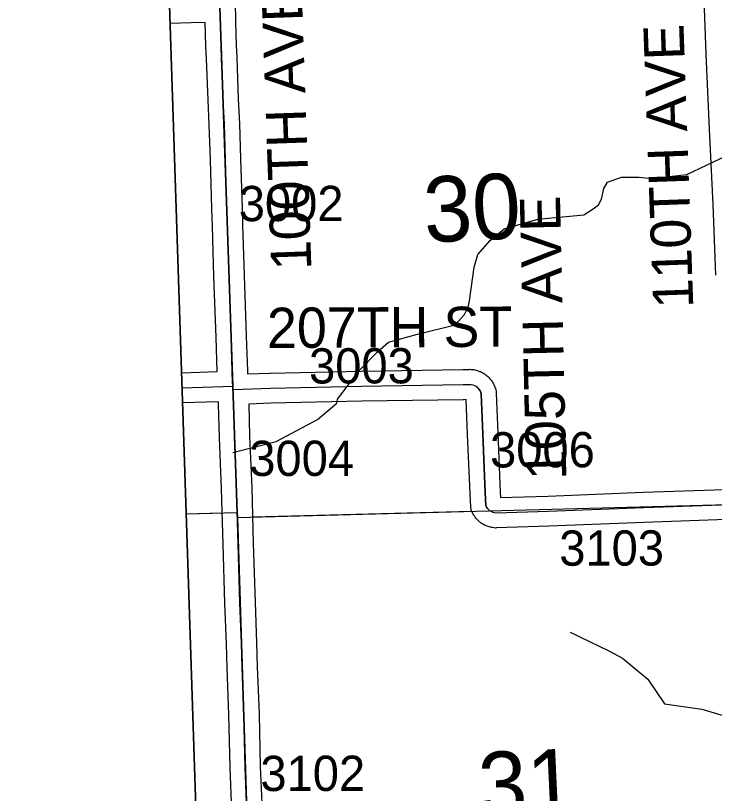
# Model space of a CAD drawing. Extents: x 128.7 to 185.5, y -21.4 to 12.6.
# Drawn here: x 133.689 to 135.078, y -7.251 to -5.706 of the extents above; entities that cross this region are included whole.
import ezdxf

# ---------------------------------------------------------------- set-up
doc = ezdxf.new("R2010")
doc.units = 0
for name, color, linetype in [('tdCoClipBndry', 7, 'Continuous'), ('tdCoCoBndry', 7, 'Continuous'), ('tdCoHydroRiver', 7, 'Continuous'), ('tdCoSecRdNmbr', 7, 'Continuous'), ('tdCoSecRdTxt', 7, 'Continuous'), ('tdCoSecRteBand', 7, 'Continuous'), ('tdCoSecRteCL', 7, 'Continuous'), ('tdCoSectLine', 7, 'Continuous'), ('tdCoSectLinePart', 7, 'Continuous'), ('tdCoSectNmbr', 7, 'Continuous'), ('tdCoSurfGravel', 7, 'Continuous'), ('tdCoTwpBndryShd', 7, 'Continuous')]:
    doc.layers.add(name, color=color, linetype=linetype)

msp = doc.modelspace()

# ---------------------------------------------------------------- linework, layer by layer
at = {"layer": 'tdCoClipBndry'}
msp.add_lwpolyline([(134.0612, -7.7025), (133.8962, -2.6807), (133.6887, 4.3446), (133.6938, 4.3792), (133.7053, 4.4028), (133.7226, 4.4226), (133.7445, 4.4372), (133.7868, 4.4475), (134.771, 4.4649), (135.7559, 4.4935), (136.7866, 4.5129), (139.7725, 4.5879), (146.7594, 4.806), (147.7608, 4.8492), (149.7557, 4.9088), (150.75, 4.946), (153.7332, 5.0633)], dxfattribs=at)
at = {"layer": 'tdCoCoBndry'}
for p, q in [((134.095, -5.6895), (134.1294, -6.6932)), ((134.1294, -6.6932), (134.095, -5.6895)), ((134.1294, -6.6932), (134.1297, -6.7029)), ((134.1297, -6.7029), (134.1294, -6.6932)), ((134.1297, -6.7029), (134.1615, -7.6994)), ((134.1615, -7.6994), (134.1297, -6.7029))]:
    msp.add_line(p, q, dxfattribs=at)
for points in [[(134.1615, -7.6994), (134.1297, -6.7029), (134.1294, -6.6932), (134.095, -5.6895), (134.0611, -4.6883), (134.0307, -3.6816), (133.9965, -2.6778), (133.9676, -1.6731), (133.9395, -0.6703), (133.9071, 0.3357), (133.8784, 1.3376), (133.8476, 2.341), (133.8192, 3.3421), (133.789, 4.3475), (134.7737, 4.365), (135.7592, 4.3936), (135.7859, 4.3937), (136.7735, 4.4131), (136.7891, 4.4129), (137.7728, 4.4375)], [(133.7886, 4.3475), (133.8188, 3.3421), (133.8473, 2.341), (133.878, 1.3376), (133.9067, 0.3357), (133.9391, -0.6703), (133.9673, -1.6731), (133.9961, -2.6778), (134.0303, -3.6816), (134.0608, -4.6883), (134.0947, -5.6895), (134.129, -6.6932), (134.1293, -6.7029), (134.1612, -7.6994), (134.1875, -8.683), (134.2186, -9.7062), (134.2417, -10.7094), (134.275, -11.7191), (134.2997, -12.7212), (134.329, -13.723)], [(134.1615, -7.6994), (134.1297, -6.7029), (134.1294, -6.6932), (134.095, -5.6895), (134.0611, -4.6883), (134.0307, -3.6816), (133.9965, -2.6778), (133.9676, -1.6731), (133.8665, -1.6741), (133.8962, -2.6807), (134.0612, -7.7025)]]:
    msp.add_lwpolyline(points, dxfattribs=at)
at = {"layer": 'tdCoHydroRiver'}
for points in [[(134.1206, -6.5738), (134.2067, -6.5523), (134.2891, -6.5088), (134.3275, -6.4761), (134.3289, -6.4682), (134.3729, -6.4101), (134.4082, -6.3743), (134.4297, -6.3547), (134.4876, -6.3388), (134.5628, -6.3208), (134.5811, -6.2997), (134.5886, -6.2853), (134.5913, -6.2726), (134.6004, -6.206), (134.6075, -6.1806), (134.632, -6.153), (134.6597, -6.1301), (134.727, -6.1107), (134.8182, -6.1017), (134.8368, -6.0901), (134.8476, -6.0819), (134.8536, -6.0707), (134.8577, -6.05), (134.8652, -6.0372), (134.8933, -6.0269), (134.928, -6.0274), (134.9535, -6.0299), (135.0229, -6.0218), (135.101, -5.9851)], [(134.791, -6.9308), (134.8679, -6.968), (134.8952, -6.9829), (134.9453, -7.0241), (134.9783, -7.0736), (135.0528, -7.084), (135.126, -7.1055)]]:
    msp.add_lwpolyline(points, dxfattribs=at)
at = {"layer": 'tdCoSecRteBand'}
for points in [[(135.0807, -6.2218), (135.0753, -6.0816), (135.0682, -5.932), (135.0682, -5.932), (135.0682, -5.9319), (135.0615, -5.7827), (135.0615, -5.7826), (135.0615, -5.7825), (135.0568, -5.6548)], [(134.125, -5.6888), (134.1256, -5.7076), (134.1256, -5.7076), (134.1256, -5.7076), (134.1259, -5.7187), (134.1259, -5.7187), (134.127, -5.765), (134.1283, -5.7895), (134.1283, -5.7897), (134.1283, -5.7898), (134.1315, -5.8714), (134.1337, -5.9209), (134.1337, -5.9211), (134.1337, -5.9212), (134.1359, -5.9908), (134.1359, -5.9908), (134.1359, -5.9908), (134.1389, -6.0879), (134.1401, -6.1221), (134.1401, -6.1222), (134.1401, -6.1223), (134.1431, -6.2228), (134.1473, -6.3431), (134.1473, -6.3431), (134.1473, -6.3432), (134.1495, -6.4116), (134.1497, -6.4116), (134.1499, -6.4179), (134.1943, -6.4162), (134.1946, -6.4162), (134.1948, -6.4162), (134.3756, -6.4122), (134.3757, -6.4122), (134.3758, -6.4122), (134.5776, -6.4093), (134.5873, -6.409), (134.5902, -6.4089), (134.5922, -6.4088), (134.5942, -6.409), (134.5974, -6.4093), (134.5993, -6.4095), (134.6013, -6.4099), (134.6044, -6.4106), (134.6063, -6.4111), (134.6082, -6.4118), (134.6111, -6.4129), (134.613, -6.4135), (134.6147, -6.4145), (134.6175, -6.416), (134.6193, -6.4169), (134.6209, -6.418), (134.6215, -6.4185), (134.6215, -6.4185), (134.6215, -6.4185), (134.6235, -6.4199), (134.6251, -6.421), (134.6266, -6.4224), (134.6289, -6.4246), (134.6303, -6.4259), (134.6316, -6.4275), (134.6336, -6.4299), (134.6348, -6.4314), (134.6359, -6.4331), (134.6375, -6.4358), (134.6386, -6.4375), (134.6394, -6.4393), (134.6407, -6.4422), (134.6415, -6.444), (134.6421, -6.4459), (134.643, -6.449), (134.6441, -6.4526), (134.6442, -6.4564), (134.6472, -6.536), (134.6521, -6.6528), (134.6527, -6.6637)], [(134.019, -6.4157), (134.0895, -6.4135), (134.0873, -6.3452), (134.0831, -6.2249), (134.0831, -6.2248), (134.0831, -6.2247), (134.0801, -6.1242), (134.0789, -6.09), (134.0789, -6.0899), (134.0789, -6.0898), (134.076, -5.9927), (134.0737, -5.9234), (134.0715, -5.874), (134.0715, -5.8739), (134.0715, -5.8738), (134.0683, -5.7923), (134.0671, -5.7676), (134.0671, -5.7672), (134.0671, -5.7669), (134.0659, -5.72), (134.0379, -5.7206), (133.9962, -5.7218)], [(134.1186, -7.2875), (134.1152, -7.2001), (134.1152, -7.1998), (134.1152, -7.1996), (134.1127, -7.0952), (134.1092, -7.0017), (134.1092, -7.0016), (134.1092, -7.0016), (134.1078, -6.9543), (134.1048, -6.8737), (134.1048, -6.8737), (134.1048, -6.8736), (134.1011, -6.7569), (134.1011, -6.7569), (134.1011, -6.7568), (134.0981, -6.6463), (134.094, -6.5449), (134.094, -6.5447), (134.0939, -6.5444), (134.0922, -6.478), (134.092, -6.4734), (134.0209, -6.4757)], [(135.1015, -6.7074), (134.9384, -6.7131), (134.7488, -6.7205), (134.7487, -6.7205), (134.7486, -6.7205), (134.6448, -6.724), (134.6425, -6.7241), (134.6403, -6.7238), (134.637, -6.7234), (134.635, -6.7232), (134.6329, -6.7226), (134.6298, -6.7218), (134.6278, -6.7213), (134.6258, -6.7205), (134.6228, -6.7192), (134.6209, -6.7184), (134.6191, -6.7173), (134.6163, -6.7156), (134.6145, -6.7146), (134.6129, -6.7133), (134.6115, -6.7122), (134.6104, -6.7112), (134.6087, -6.7099), (134.6073, -6.7084), (134.6051, -6.706), (134.6036, -6.7045), (134.6024, -6.7028), (134.6006, -6.7001), (134.5993, -6.6984), (134.5984, -6.6966), (134.5969, -6.6937), (134.594, -6.688), (134.5936, -6.6817), (134.5922, -6.656), (134.5921, -6.6558), (134.5921, -6.6556), (134.5872, -6.5384), (134.5872, -6.5384), (134.5872, -6.5383), (134.5846, -6.4691), (134.5789, -6.4693), (134.5788, -6.4693), (134.5787, -6.4693), (134.3768, -6.4722), (134.1964, -6.4762), (134.1522, -6.4779), (134.1539, -6.5426), (134.1581, -6.644), (134.1581, -6.6442), (134.1581, -6.6445), (134.1611, -6.7551), (134.1648, -6.8716), (134.1677, -6.9522), (134.1677, -6.9523), (134.1677, -6.9523), (134.1692, -6.9996), (134.1727, -7.0932), (134.1727, -7.0934), (134.1727, -7.0936), (134.1751, -7.1979), (134.1786, -7.2855)], [(134.6527, -6.6637), (134.7466, -6.6606), (134.9361, -6.6532), (134.9362, -6.6532), (134.9362, -6.6532), (135.0986, -6.6475)]]:
    msp.add_lwpolyline(points, dxfattribs=at)
at = {"layer": 'tdCoSecRteCL'}
for p in [(134.0199, -6.4457), (134.1211, -6.449)]:
    msp.add_line(p, (134.1207, -6.4425), dxfattribs=at)
for points in [[(134.1207, -6.4425), (134.1202, -6.4351), (134.1173, -6.3442), (134.1131, -6.2238), (134.1101, -6.1232), (134.1089, -6.0889), (134.1059, -5.9917), (134.1037, -5.9222), (134.1015, -5.8726), (134.0983, -5.791), (134.0971, -5.7661), (134.0956, -5.7084), (134.095, -5.6895)], [(134.1211, -6.449), (134.1955, -6.4462), (134.3762, -6.4422), (134.5782, -6.4393), (134.5883, -6.439), (134.5915, -6.4389), (134.5946, -6.4392), (134.5977, -6.4399), (134.6007, -6.441), (134.6035, -6.4425), (134.6041, -6.4429), (134.6061, -6.4443), (134.6084, -6.4465), (134.6104, -6.4489), (134.612, -6.4516), (134.6133, -6.4545), (134.6142, -6.4575), (134.6172, -6.5372), (134.6221, -6.6543), (134.6236, -6.68), (134.6251, -6.6828), (134.6269, -6.6855), (134.6292, -6.6879), (134.6303, -6.6888), (134.6317, -6.6899), (134.6345, -6.6915), (134.6375, -6.6928), (134.6406, -6.6936), (134.6438, -6.694), (134.7476, -6.6906), (134.9373, -6.6832), (135.1299, -6.6764)], [(134.1486, -7.2867), (134.1451, -7.1989), (134.1427, -7.0943), (134.1392, -7.0006), (134.1377, -6.9533), (134.1348, -6.8726), (134.1311, -6.756), (134.1281, -6.6453), (134.1239, -6.5437), (134.1217, -6.4586), (134.1211, -6.449)]]:
    msp.add_lwpolyline(points, dxfattribs=at)
at = {"layer": 'tdCoSectLine'}
for points in [[(134.0947, -5.6895), (134.129, -6.6932)], [(134.1293, -6.7029), (135.1295, -6.6764)], [(134.0282, -6.6961), (134.129, -6.6932)], [(134.129, -6.6932), (134.1293, -6.7029)], [(134.1293, -6.7029), (134.1612, -7.6994)]]:
    msp.add_lwpolyline(points, dxfattribs=at)
at = {"layer": 'tdCoSectLinePart'}
for points in [[(134.1596, -6.7021), (134.5957, -6.6906)], [(134.0282, -6.6961), (134.099, -6.6941)]]:
    msp.add_lwpolyline(points, dxfattribs=at)
at = {"layer": 'tdCoSurfGravel'}
msp.add_line((134.0199, -6.4457), (134.1207, -6.4425), dxfattribs=at)
for points in [[(134.1486, -7.2867), (134.1451, -7.1989), (134.1427, -7.0943), (134.1392, -7.0006), (134.1377, -6.9533), (134.1348, -6.8726), (134.1311, -6.756), (134.1281, -6.6453), (134.1239, -6.5437), (134.1217, -6.4586), (134.1211, -6.449), (134.1207, -6.4425), (134.1202, -6.4351), (134.1173, -6.3442), (134.1131, -6.2238), (134.1101, -6.1232), (134.1089, -6.0889), (134.1059, -5.9917), (134.1037, -5.9222), (134.1015, -5.8726), (134.0983, -5.791), (134.0971, -5.7661), (134.0956, -5.7084), (134.095, -5.6895)], [(134.1211, -6.449), (134.1955, -6.4462), (134.3762, -6.4422), (134.5782, -6.4393), (134.5883, -6.439), (134.5915, -6.4389), (134.5946, -6.4392), (134.5977, -6.4399), (134.6007, -6.441), (134.6035, -6.4425), (134.6041, -6.4429)], [(134.6303, -6.6888), (134.6292, -6.6879), (134.6269, -6.6855), (134.6251, -6.6828), (134.6236, -6.68), (134.6221, -6.6543), (134.6172, -6.5372), (134.6142, -6.4575), (134.6133, -6.4545), (134.612, -6.4516), (134.6104, -6.4489), (134.6084, -6.4465), (134.6061, -6.4443), (134.6041, -6.4429)], [(134.6303, -6.6888), (134.6317, -6.6899), (134.6345, -6.6915), (134.6375, -6.6928), (134.6406, -6.6936), (134.6438, -6.694), (134.7476, -6.6906), (134.9373, -6.6832), (135.1299, -6.6764)]]:
    msp.add_lwpolyline(points, dxfattribs=at)
at = {"layer": 'tdCoTwpBndryShd'}
msp.add_lwpolyline([(133.7886, 4.3475), (133.8188, 3.3421), (133.8473, 2.341), (133.878, 1.3376), (133.9067, 0.3357), (133.9391, -0.6703), (133.9673, -1.6731), (133.9961, -2.6778), (134.0303, -3.6816), (134.0608, -4.6883), (134.0947, -5.6895), (134.129, -6.6932), (134.1293, -6.7029), (134.1612, -7.6994)], dxfattribs=at)

# ---------------------------------------------------------------- texts
at = {"layer": 'tdCoSecRdNmbr'}
for s, rotation, p in [('3002', 0.1021, (134.1324, -6.1146)), ('3003', 0.1023, (134.2721, -6.4371)), ('3006', 0.1023, (134.6319, -6.6038)), ('3004', 0.1021, (134.1533, -6.6208)), ('3103', 0.1026, (134.7694, -6.799)), ('3102', 0.1021, (134.1754, -7.2466))]:
    msp.add_text(s, height=0.07, rotation=rotation, dxfattribs=at).set_placement(p)
at = {"layer": 'tdCoSecRdTxt'}
for s, rotation, p in [('100TH AVE', 92, (134.2769, -6.2107)), ('110TH AVE', 92, (135.036, -6.2867)), ('105TH AVE', 91.3087, (134.7837, -6.6279)), ('207TH ST', 0.3087, (134.1886, -6.3666))]:
    msp.add_text(s, height=0.08, rotation=rotation, dxfattribs=at).set_placement(p)
at = {"layer": 'tdCoSectNmbr'}
for s, p in [('30', (134.5024, -6.1571)), ('31', (134.6115, -7.3002))]:
    msp.add_text(s, height=0.13, rotation=2.6547, dxfattribs=at).set_placement(p)

doc.saveas('drawing.dxf')
